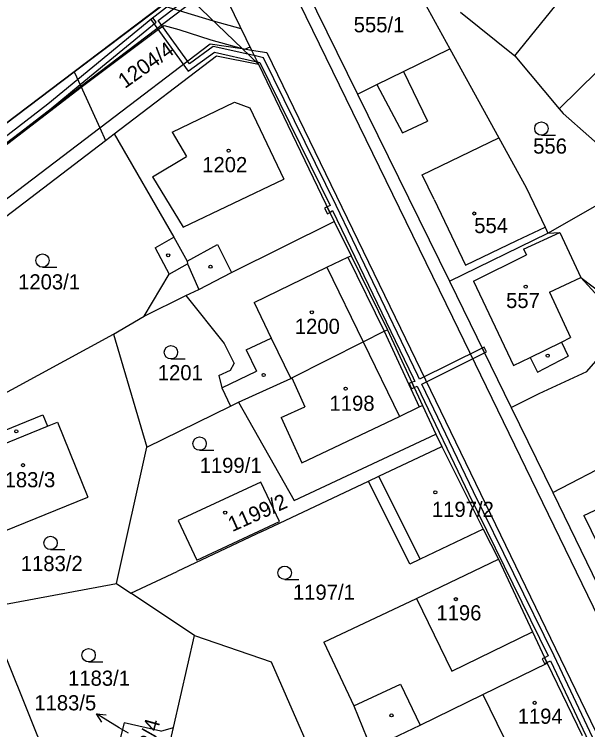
# Model space of a CAD drawing. Extents: x -785744 to -782822, y -1067550 to -1063910.
# Drawn here: x -783802 to -783737.6, y -1065686.6 to -1065606.3 of the extents above; entities that cross this region are included whole.
import ezdxf

# ---------------------------------------------------------------- set-up
doc = ezdxf.new("R2010")
doc.units = 0
for name, color, linetype in [('Hranice parcel', 7, 'Continuous'), ('Parcelní čísla', 7, 'Continuous'), ('Pop_ČP_popisy', 7, 'Continuous'), ('Vnitřní kresba', 7, 'Continuous'), ('Věcná břemena k části', 7, 'Continuous'), ('Značky budov', 7, 'Continuous'), ('Značky kultur', 7, 'Continuous')]:
    doc.layers.add(name, color=color, linetype=linetype)

msp = doc.modelspace()

# ---------------------------------------------------------------- linework, layer by layer
at = {"layer": 'Hranice parcel'}
for p, q in [((-783761.03, -1065658.12), (-783753.93, -1065654.77)), ((-783753.93, -1065654.77), (-783749.29, -1065664.04)), ((-783762.19, -1065658.67), (-783761.03, -1065658.12)), ((-783774.27, -1065658.76), (-783783.54, -1065663.09)), ((-783772.18, -1065663.2), (-783774.27, -1065658.76)), ((-783774.17, -1065664.33), (-783762.19, -1065658.67)), ((-783757.53, -1065667.97), (-783762.19, -1065658.67)), ((-783783.54, -1065663.09), (-783781.45, -1065667.55)), ((-783781.45, -1065667.55), (-783772.18, -1065663.2)), ((-783749.29, -1065664.04), (-783756.39, -1065667.43)), ((-783749.29, -1065664.04), (-783747.59, -1065667.42)), ((-783756.39, -1065667.43), (-783757.53, -1065667.97)), ((-783789.63, -1065685.78), (-783790.18, -1065687.99)), ((-783785.5, -1065686.71), (-783789.63, -1065685.78)), ((-783785.5, -1065686.71), (-783784.09, -1065686.33))]:
    msp.add_line(p, q, dxfattribs=at)
for points in [[(-783745.75, -1065610.93), (-783734.85, -1065597.44)], [(-783780.51, -1065599.54), (-783775.31, -1065610.27)], [(-783757.99, -1065601.12), (-783753.03, -1065610.12)], [(-783795.22, -1065612.71), (-783782.97, -1065603.45)], [(-783769.19, -1065603.48), (-783763.4, -1065615.22)], [(-783781.91, -1065604.78), (-783776.37, -1065610.11)], [(-783751.85, -1065606.03), (-783745.75, -1065610.93)], [(-783776.37, -1065610.11), (-783774.54, -1065611.87)], [(-783758.26, -1065612.69), (-783753.03, -1065610.12)], [(-783753.03, -1065610.12), (-783747.53, -1065620.13)], [(-783790.75, -1065619.67), (-783779.26, -1065610.91)], [(-783779.26, -1065610.91), (-783774.54, -1065611.87)], [(-783775.31, -1065610.27), (-783774.54, -1065611.87)], [(-783745.75, -1065610.93), (-783740.75, -1065616.87)], [(-783740.75, -1065616.87), (-783734.32, -1065610.53)], [(-783774.54, -1065611.87), (-783766.03, -1065629.51)], [(-783808.23, -1065622.53), (-783795.22, -1065612.71)], [(-783795.22, -1065612.71), (-783794.48, -1065614.34)], [(-783761.23, -1065614.15), (-783758.26, -1065612.69)], [(-783763.4, -1065615.22), (-783761.23, -1065614.15)], [(-783794.48, -1065614.34), (-783792.36, -1065618.99)], [(-783763.4, -1065615.22), (-783753.06, -1065636.23)], [(-783740.75, -1065616.87), (-783740.32, -1065617.38)], [(-783740.32, -1065617.38), (-783731.67, -1065625.04)], [(-783792.36, -1065618.99), (-783791.72, -1065620.41)], [(-783791.72, -1065620.41), (-783790.75, -1065619.67)], [(-783790.75, -1065619.67), (-783784.03, -1065631.26)], [(-783814.22, -1065637.55), (-783791.72, -1065620.41)], [(-783747.53, -1065620.13), (-783744.46, -1065625.71)], [(-783744.46, -1065625.71), (-783742.35, -1065630.17)], [(-783742.05, -1065630.82), (-783734.35, -1065626.44)], [(-783777.58, -1065635.26), (-783766.03, -1065629.51)], [(-783766.03, -1065629.51), (-783764.13, -1065633.36)], [(-783742.35, -1065630.17), (-783742.05, -1065630.82)], [(-783753.06, -1065636.23), (-783742.05, -1065630.82)], [(-783742.05, -1065630.82), (-783740.68, -1065630.74)], [(-783740.68, -1065630.74), (-783738.32, -1065635.81)], [(-783786.12, -1065632.47), (-783784.03, -1065631.26)], [(-783786.12, -1065632.47), (-783784.58, -1065635.42)], [(-783764.13, -1065633.36), (-783760.05, -1065641.67)], [(-783787.37, -1065640.15), (-783784.58, -1065635.42)], [(-783781.22, -1065637.14), (-783777.58, -1065635.26)], [(-783738.32, -1065635.81), (-783733.15, -1065641.45)], [(-783738.32, -1065635.81), (-783720.69, -1065649.16)], [(-783753.06, -1065636.23), (-783746.14, -1065650.38)], [(-783782.68, -1065637.81), (-783781.22, -1065637.14)], [(-783787.37, -1065640.15), (-783782.68, -1065637.81)], [(-783782.68, -1065637.81), (-783778.4, -1065643.21)], [(-783790.8, -1065642.17), (-783787.37, -1065640.15)], [(-783807.79, -1065651.36), (-783790.8, -1065642.17)], [(-783790.8, -1065642.17), (-783787.06, -1065654.83)], [(-783762.77, -1065643.01), (-783760.4, -1065641.84)], [(-783760.4, -1065641.84), (-783760.05, -1065641.67)], [(-783760.05, -1065641.67), (-783756.1, -1065650.17)], [(-783770.79, -1065647.08), (-783762.77, -1065643.01)], [(-783778.4, -1065643.21), (-783777.26, -1065645.47)], [(-783737.65, -1065646.36), (-783735.91, -1065644.33)], [(-783777.68, -1065646.22), (-783777.26, -1065645.47)], [(-783779, -1065646.8), (-783777.68, -1065646.22)], [(-783779, -1065646.8), (-783778.65, -1065648.17)], [(-783776.77, -1065649.81), (-783770.9, -1065647.13)], [(-783770.9, -1065647.13), (-783770.79, -1065647.08)], [(-783743.02, -1065648.84), (-783737.65, -1065646.36)], [(-783778.65, -1065648.17), (-783777.69, -1065650.24)], [(-783746.14, -1065650.38), (-783743.02, -1065648.84)], [(-783741.47, -1065659.94), (-783720.69, -1065649.16)], [(-783787.06, -1065654.83), (-783777.69, -1065650.24)], [(-783777.69, -1065650.24), (-783776.77, -1065649.81)], [(-783776.77, -1065649.81), (-783770.51, -1065660.83)], [(-783756.1, -1065650.17), (-783754.61, -1065653.4)], [(-783746.14, -1065650.38), (-783741.47, -1065659.94)], [(-783804.94, -1065653.73), (-783798.75, -1065651.22)], [(-783798.75, -1065651.22), (-783798.23, -1065652.5)], [(-783798.23, -1065652.5), (-783797.1, -1065652.04)], [(-783797.1, -1065652.04), (-783793.69, -1065660.45)], [(-783770.51, -1065660.83), (-783754.61, -1065653.4)], [(-783754.61, -1065653.4), (-783753.93, -1065654.77)], [(-783790.49, -1065670.17), (-783787.06, -1065654.83)], [(-783737.99, -1065662.51), (-783730.71, -1065659.1)], [(-783741.47, -1065659.94), (-783735.78, -1065671.66)], [(-783804.32, -1065664.76), (-783793.69, -1065660.45)], [(-783737.99, -1065662.51), (-783733.96, -1065670.77)], [(-783774.17, -1065664.33), (-783783.68, -1065668.8)], [(-783756.78, -1065671.85), (-783747.59, -1065667.42)], [(-783747.59, -1065667.42), (-783743.76, -1065675.59)], [(-783788.87, -1065671.24), (-783783.68, -1065668.8)], [(-783805.19, -1065672.87), (-783790.49, -1065670.17)], [(-783790.49, -1065670.17), (-783788.87, -1065671.24)], [(-783781.7, -1065675.98), (-783788.87, -1065671.24)], [(-783767.2, -1065676.72), (-783756.78, -1065671.85)], [(-783784.09, -1065686.33), (-783781.7, -1065675.98)], [(-783781.7, -1065675.98), (-783773.12, -1065678.94)], [(-783743.76, -1065675.59), (-783742.11, -1065679.11)], [(-783767.2, -1065676.72), (-783763.81, -1065683.87)], [(-783802.85, -1065678.62), (-783798.18, -1065690.17)], [(-783773.12, -1065678.94), (-783767.79, -1065691.11)], [(-783749.33, -1065682.61), (-783742.11, -1065679.11)], [(-783742.11, -1065679.11), (-783738.16, -1065687.2)], [(-783756.37, -1065686.04), (-783749.33, -1065682.61)], [(-783749.33, -1065682.61), (-783745.36, -1065690.72)], [(-783763.81, -1065683.87), (-783761.88, -1065688.68)], [(-783786.75, -1065697.81), (-783784.09, -1065686.33)], [(-783761.88, -1065688.68), (-783756.37, -1065686.04)]]:
    msp.add_lwpolyline(points, dxfattribs=at)
at = {"layer": 'Pop_ČP_popisy'}
msp.add_line((-783790.17, -1065686.34), (-783792.736, -1065684.786), dxfattribs=at)
for points in [[(-783792.14, -1065685.732), (-783792.736, -1065684.786), (-783791.622, -1065684.876)], [(-783789.12, -1065686.97), (-783790.17, -1065686.34)]]:
    msp.add_lwpolyline(points, dxfattribs=at)
at = {"layer": 'Vnitřní kresba'}
msp.add_line((-783756.39, -1065667.43), (-783761.03, -1065658.12), dxfattribs=at)
for points in [[(-783775.22, -1065594.2), (-783752.74, -1065640.26)], [(-783794.48, -1065614.34), (-783781.91, -1065604.78)], [(-783792.36, -1065618.99), (-783779.94, -1065609.56)], [(-783779.94, -1065609.56), (-783776.37, -1065610.11)], [(-783776.37, -1065610.11), (-783775.31, -1065610.27)], [(-783775.31, -1065610.27), (-783773.58, -1065610.54)], [(-783773.58, -1065610.54), (-783758.57, -1065641.49)], [(-783758.26, -1065612.69), (-783755.54, -1065618.26)], [(-783761.23, -1065614.15), (-783758.36, -1065619.55)], [(-783820.49, -1065634.13), (-783794.48, -1065614.34)], [(-783784.24, -1065619.48), (-783777.23, -1065616.12)], [(-783777.23, -1065616.12), (-783775.49, -1065616.74)], [(-783775.49, -1065616.74), (-783771.67, -1065624.76)], [(-783817.48, -1065638.08), (-783792.36, -1065618.99)], [(-783758.36, -1065619.55), (-783755.54, -1065618.26)], [(-783784.24, -1065619.48), (-783782.61, -1065622.23)], [(-783756.13, -1065624.28), (-783747.53, -1065620.13)], [(-783786.45, -1065624.5), (-783782.61, -1065622.23)], [(-783786.45, -1065624.5), (-783782.98, -1065630.15)], [(-783754.81, -1065627.06), (-783756.13, -1065624.28)], [(-783782.98, -1065630.15), (-783771.67, -1065624.76)], [(-783754.81, -1065627.06), (-783751.29, -1065634.41)], [(-783745.51, -1065631.66), (-783742.35, -1065630.17)], [(-783744.75, -1065632.62), (-783740.68, -1065630.74)], [(-783784.03, -1065631.26), (-783782.56, -1065633.96)], [(-783751.29, -1065634.41), (-783745.51, -1065631.66)], [(-783782.56, -1065633.96), (-783779.15, -1065632.11)], [(-783779.15, -1065632.11), (-783777.58, -1065635.26)], [(-783744.75, -1065632.62), (-783744.43, -1065633.26)], [(-783764.49, -1065633.53), (-783764.13, -1065633.36)], [(-783750.38, -1065636.2), (-783744.43, -1065633.26)], [(-783784.58, -1065635.42), (-783782.52, -1065634.28)], [(-783782.56, -1065633.96), (-783782.52, -1065634.28)], [(-783782.52, -1065634.28), (-783781.22, -1065637.14)], [(-783766.86, -1065634.63), (-783764.49, -1065633.53)], [(-783764.49, -1065633.53), (-783760.4, -1065641.84)], [(-783775.01, -1065638.62), (-783766.86, -1065634.63)], [(-783766.86, -1065634.63), (-783762.77, -1065643.01)], [(-783741.84, -1065637.45), (-783738.32, -1065635.81)], [(-783750.38, -1065636.2), (-783745.87, -1065645.69)], [(-783741.84, -1065637.45), (-783739.47, -1065642.54)], [(-783775.01, -1065638.62), (-783773.1, -1065642.6)], [(-783752.74, -1065640.26), (-783731.25, -1065684.5)], [(-783758.57, -1065641.49), (-783736.66, -1065686.71)], [(-783760.4, -1065641.84), (-783756.47, -1065650.33)], [(-783775.9, -1065643.94), (-783773.1, -1065642.6)], [(-783773.1, -1065642.6), (-783770.9, -1065647.13)], [(-783762.77, -1065643.01), (-783758.7, -1065651.39)], [(-783744.01, -1065644.77), (-783740.51, -1065643.05)], [(-783740.51, -1065643.05), (-783739.47, -1065642.54)], [(-783740.51, -1065643.05), (-783739.74, -1065644.63)], [(-783775.9, -1065643.94), (-783774.76, -1065646.31)], [(-783743.21, -1065646.42), (-783739.74, -1065644.63)], [(-783745.87, -1065645.69), (-783744.01, -1065644.77)], [(-783744.01, -1065644.77), (-783743.21, -1065646.42)], [(-783778.65, -1065648.17), (-783774.76, -1065646.31)], [(-783770.79, -1065647.08), (-783769.32, -1065650.31)], [(-783771.98, -1065651.53), (-783769.32, -1065650.31)], [(-783758.7, -1065651.39), (-783756.47, -1065650.33)], [(-783756.47, -1065650.33), (-783756.1, -1065650.17)], [(-783771.98, -1065651.53), (-783769.67, -1065656.59)], [(-783769.67, -1065656.59), (-783758.7, -1065651.39)], [(-783804.41, -1065655.01), (-783798.23, -1065652.5)], [(-783756.78, -1065671.85), (-783752.81, -1065679.99)], [(-783752.81, -1065679.99), (-783743.76, -1065675.59)], [(-783763.81, -1065683.87), (-783758.59, -1065681.45)], [(-783758.59, -1065681.45), (-783756.37, -1065686.04)]]:
    msp.add_lwpolyline(points, dxfattribs=at)
at = {"layer": 'Věcná břemena k části'}
for points in [[(-783782.7, -1065603.78), (-783786.62, -1065606.84)], [(-783785.8, -1065606.96), (-783782.33, -1065604.25), (-783782.08, -1065604.06)], [(-783785.37, -1065605.26), (-783795.22, -1065612.71)], [(-783779.58, -1065607.02), (-783785.37, -1065605.26)], [(-783786.4, -1065606.67), (-783794.82, -1065613.58)], [(-783786.62, -1065606.84), (-783782.42, -1065612.65)], [(-783786.02, -1065607.13), (-783786.4, -1065606.67)], [(-783782.28, -1065611.81), (-783785.8, -1065606.96)], [(-783794.57, -1065614.15), (-783786.02, -1065607.13)], [(-783785.63, -1065607.83), (-783785.14, -1065607.5)], [(-783785.14, -1065607.5), (-783783.47, -1065607.98)], [(-783776.46, -1065607.9), (-783779.58, -1065607.02)], [(-783794.43, -1065614.45), (-783785.63, -1065607.83)], [(-783783.47, -1065607.98), (-783779.88, -1065609.11)], [(-783775.48, -1065609.92), (-783776.46, -1065607.9)], [(-783779.88, -1065609.11), (-783776.37, -1065610.11)], [(-783779.63, -1065609.87), (-783782.28, -1065611.81)], [(-783775.71, -1065610.75), (-783779.63, -1065609.87)], [(-783776.37, -1065610.11), (-783776.08, -1065610.18)], [(-783776.08, -1065610.18), (-783775.48, -1065609.92)], [(-783782.42, -1065612.65), (-783779.49, -1065610.51)], [(-783779.49, -1065610.51), (-783774.88, -1065611.55)], [(-783773.95, -1065611.14), (-783775.01, -1065610.9), (-783775.71, -1065610.75)], [(-783774.88, -1065611.55), (-783774.67, -1065611.59)], [(-783774.67, -1065611.59), (-783774.37, -1065611.66)], [(-783774.37, -1065611.66), (-783766.49, -1065627.73)], [(-783765.82, -1065627.73), (-783773.95, -1065611.14)], [(-783795.22, -1065612.71), (-783808.23, -1065622.53)], [(-783794.82, -1065613.58), (-783798.2, -1065616.36)], [(-783797.82, -1065616.82), (-783794.57, -1065614.15)], [(-783796.38, -1065615.92), (-783794.43, -1065614.45)], [(-783798.2, -1065616.36), (-783810.26, -1065625.63)], [(-783806.78, -1065623.86), (-783796.38, -1065615.92)], [(-783810.15, -1065626.31), (-783797.82, -1065616.82)], [(-783766.83, -1065627.86), (-783767.13, -1065628.03)], [(-783766.49, -1065627.73), (-783766.83, -1065627.86), (-783766.51, -1065628.51), (-783766.23, -1065628.27)], [(-783766.51, -1065628.51), (-783766.83, -1065627.86)], [(-783756.63, -1065646.79), (-783765.82, -1065627.73)], [(-783767.13, -1065628.03), (-783766.79, -1065628.67)], [(-783766.79, -1065628.67), (-783766.51, -1065628.51)], [(-783766.23, -1065628.27), (-783757.17, -1065647.05), (-783756.98, -1065647.47)], [(-783749.39, -1065643.73), (-783756.43, -1065647.23)], [(-783749.18, -1065643.62), (-783749.39, -1065643.73)], [(-783749.13, -1065644.27), (-783749.39, -1065643.73)], [(-783749.39, -1065643.73), (-783749.13, -1065644.27)], [(-783748.91, -1065644.15), (-783749.18, -1065643.62)], [(-783756.17, -1065647.78), (-783749.13, -1065644.27)], [(-783749.13, -1065644.27), (-783748.91, -1065644.15)], [(-783756.43, -1065647.23), (-783756.63, -1065646.79)], [(-783757.31, -1065647.57), (-783757.61, -1065647.7)], [(-783757.61, -1065647.7), (-783757.34, -1065648.3)], [(-783756.98, -1065647.47), (-783757.31, -1065647.57)], [(-783757.31, -1065647.57), (-783757.03, -1065648.16)], [(-783757.03, -1065648.16), (-783757.31, -1065647.57)], [(-783750.37, -1065659.87), (-783756.17, -1065647.78)], [(-783757.34, -1065648.3), (-783757.03, -1065648.16)], [(-783757.03, -1065648.16), (-783756.72, -1065648.02)], [(-783756.72, -1065648.02), (-783750.91, -1065660.13)], [(-783741.33, -1065678.28), (-783750.37, -1065659.87)], [(-783750.91, -1065660.13), (-783742, -1065678.27)], [(-783742, -1065678.27), (-783742.41, -1065678.48)], [(-783735.43, -1065690.73), (-783741.33, -1065678.28)], [(-783742.41, -1065678.48), (-783742.68, -1065678.62)], [(-783742.68, -1065678.62), (-783742.41, -1065679.15)], [(-783742.41, -1065678.48), (-783742.15, -1065679.02), (-783741.74, -1065678.82)], [(-783742.15, -1065679.02), (-783742.41, -1065678.48)], [(-783742.41, -1065679.15), (-783742.15, -1065679.02)], [(-783741.74, -1065678.82), (-783736.1, -1065690.71)]]:
    msp.add_lwpolyline(points, dxfattribs=at)
at = {"layer": 'Značky budov'}
for centre in [(-783777.89, -1065621.56), (-783750.3, -1065628.62), (-783784.68, -1065633.31), (-783779.92, -1065634.59), (-783744.52, -1065636.83), (-783768.54, -1065639.71), (-783742.04, -1065644.57), (-783773.96, -1065646.74), (-783764.75, -1065648.28), (-783801.73, -1065653.08), (-783800.99, -1065656.87), (-783754.67, -1065659.91), (-783778.27, -1065662.19), (-783752.36, -1065671.91), (-783743.51, -1065683.55), (-783759.59, -1065684.96)]:
    msp.add_circle(centre, 0.175, dxfattribs=at)
at = {"layer": 'Značky kultur'}
for p, q in [((-783742.76, -1065619.83), (-783741.16, -1065619.83)), ((-783798.79, -1065634.65), (-783797.19, -1065634.65)), ((-783784.36, -1065644.95), (-783782.76, -1065644.95)), ((-783781.14, -1065655.2), (-783779.54, -1065655.2)), ((-783797.89, -1065666.35), (-783796.29, -1065666.35)), ((-783771.59, -1065669.7), (-783769.99, -1065669.7)), ((-783793.61, -1065678.95), (-783792.01, -1065678.95))]:
    msp.add_line(p, q, dxfattribs=at)
for centre in [(-783742.76, -1065619.08), (-783798.79, -1065633.9), (-783784.36, -1065644.2), (-783781.14, -1065654.45), (-783797.89, -1065665.6), (-783771.59, -1065668.95), (-783793.61, -1065678.2)]:
    msp.add_circle(centre, 0.75, dxfattribs=at)

# ---------------------------------------------------------------- texts
at = {"layer": 'Parcelní čísla'}
for s, p in [('555/1', (-783763.84, -1065608.28)), ('556', (-783743.68, -1065621.9)), ('1202', (-783780.85, -1065623.98)), ('554', (-783750.3, -1065630.82)), ('1203/1', (-783801.53, -1065637.14)), ('557', (-783746.72, -1065639.23)), ('1200', (-783770.45, -1065642.13)), ('1201', (-783785.84, -1065647.33)), ('1198', (-783766.55, -1065650.77)), ('1199/1', (-783781.14, -1065657.74)), ('1183/3', (-783804.31, -1065659.35)), ('1197/2', (-783755.05, -1065662.68)), ('1183/2', (-783801.23, -1065668.76)), ('1197/1', (-783770.66, -1065671.98)), ('1196', (-783754.55, -1065674.29)), ('1183/1', (-783795.92, -1065681.63)), ('1194', (-783745.42, -1065685.9))]:
    msp.add_text(s, height=1.7, dxfattribs=at).set_placement(p)
for s, rotation, p in [('1204/4', 35.55945, (-783789.53, -1065614.65)), ('1199/2', 23.9724, (-783777.48, -1065664.39)), ('1182/4', 74.58543, (-783787.39, -1065692.33))]:
    msp.add_text(s, height=1.7, rotation=rotation, dxfattribs=at).set_placement(p)
at = {"layer": 'Pop_ČP_popisy'}
msp.add_text('1183/5', height=1.7, dxfattribs=at).set_placement((-783799.71, -1065684.39))

doc.saveas('drawing.dxf')
